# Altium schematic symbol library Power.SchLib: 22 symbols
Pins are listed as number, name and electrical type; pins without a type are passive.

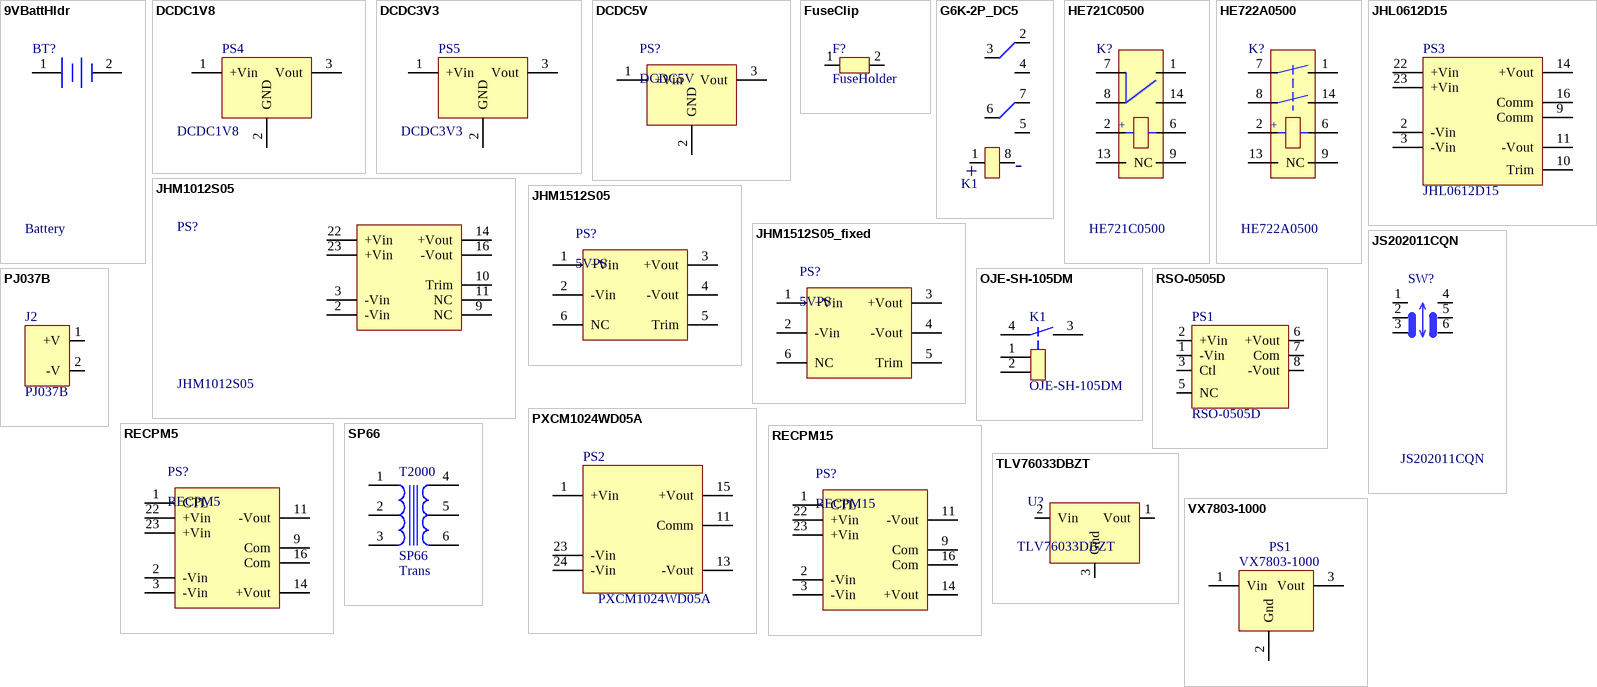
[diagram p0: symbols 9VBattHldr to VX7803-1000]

## 9VBattHldr
designator BT?, comment Battery
Battery Holder (Open) 9V 1 Cell PC Pin; MFG PN: BH9VPC; DK PN: BH9V-PC-ND; MFG: MPD
footprint 9VBattHolder
pins: 1 +, 2 -

## DCDC1V8
designator PS4
Linear Regulator Replacement DC DC Converter 1 Output 1.8V 500mA 4.75V - 28V Input; MFG PN: P7805-Q12-S1R8-S; DK PN: 102-2985-5-ND; MFG: CUI
footprint CUI_P7805
pins: 1 +Vin (power), 2 GND (power), 3 Vout (power)

## DCDC3V3
designator PS5
Linear Regulator Replacement DC DC Converter 1 Output 3.3V 500mA 4.75V - 28V Input; MFG PN: P7805-Q24-S3-S; DK PN: 102-2704-ND; MFG: CUI
footprint CUI_P7805
pins: 1 +Vin (power), 2 GND (power), 3 Vout (power)

## DCDC5V
designator PS?  Comment_1: DCDC5V  (hidden comment: *)
Linear Regulator Replacement DC DC Converter 1 Output 5V 500mA 6.5V - 32V Input; MFG PN: P7805-Q24-S5-S; DK PN: 102-2705-ND; MFG: CUI
footprint CUI_P7805
pins: 1 +Vin (power), 2 GND (power), 3 Vout (power)

## FuseClip
designator F?, comment FuseHolder
Fuse Holder 5A 250V 1 Circuit Cartridge PCB; MFG PN: 4527; MFG: Keystone Electronics; DK PN: 36-4527-ND
footprint FuseClip
pins: 1, 2

## G6K-2P_DC5
designator K1  (value not drawn)
Telecom Relay DPDT (2 Form C) Through Hole; MFG PN: G6K-2P DC5; DK PN: Z116-ND; MFG: Omron
footprint G6K-2P
pins: 1, 2, 3, 4, 5, 6, 7, 8

## HE721C0500
designator K?
RELAY REED SPDT 250MA 5V; DK PN: HE112-ND; MFG: Littlefuse
footprint HE7X
pins: 1, 2, 6, 7, 8, 9, 13 NC, 14

## HE722A0500
designator K?
RELAY REED DPST 500MA 5V; DK PN: HE554-ND; MFG: Littlefuse
footprint HE7X
pins: 1, 2, 6, 7, 8, 9, 13 NC, 14

## JHL0612D15
designator PS3
Isolated Module DC DC Converter 2 Output 15V -15V 200mA, 200mA 10V - 17V Input; MFG: XP Power; DK PN: 1470-3037-5-ND
footprint JHL06
pins: 2 -Vin, 3 -Vin, 9 Comm, 10 Trim, 11 -Vout, 14 +Vout, 16 Comm, 22 +Vin, 23 +Vin

## JHM1012S05
designator PS?
Isolated Module DC DC Converter 1 Output 5V 2A 9V - 18V Input; MFG: XP Power; DK PN: 1470-2051-5-ND
footprint JHM10
pins: 2 -Vin, 3 -Vin, 9 NC, 10 Trim, 11 NC, 14 +Vout, 16 -Vout, 22 +Vin, 23 +Vin

## JHM1512S05
designator PS?, comment 5VPS
Isolated Module DC DC Converter 1 Output 5V 3A 9V - 18V Input; MFG PN: JHM1512S05; DK PN: 1470-2815-5-ND; PKG: JHM15; MFG: XP Power
footprint JMH15
pins: 1 +Vin (power), 2 -Vin (power), 3 +Vout (power), 4 -Vout (power), 5 Trim (power), 6 NC (power)

## JHM1512S05_fixed
designator PS?  Comment_1: 5VPS  (hidden comment: *)
Isolated Module DC DC Converter 1 Output 5V 3A 9V - 18V Input; MFG PN: JHM1512S05; DK PN: 1470-2815-5-ND; PKG: JHM15; MFG: XP Power
footprint JMH15_FIXED
pins: 1 +Vin (power), 2 -Vin (power), 3 +Vout (power), 4 -Vout (power), 5 Trim (power), 6 NC (power)

## JS202011CQN
designator SW?
Slide Switch DPDT Through Hole; DK PN: 401-2001-ND; MFG: C&K
footprint DPDTSlide
pins: 1 15, 2 16, 3 17, 4 18, 5 19, 6 20

## OJE-SH-105DM
designator K1
General Purpose Relay SPST-NO (1 Form A) 5VDC Coil Through Hole; MFG PN: OJE-SH-105DM,000; DK PN: PB874-ND; MFG: TE
footprint OJERELAY
pins: 1, 2, 3, 4
1 alternate drawing of the same symbol

## PJ037B
designator J2
Power Barrel Connector Jack 2.50mm ID (0.098"), 5.50mm OD (0.217") Through Hole, Right Angle; MFG PN: PJ-037B; DK PN: CP-037B-ND; MFG: CUI
footprint PJ037B
pins: 1 +V, 2 -V
1 alternate drawing of the same symbol

## PXCM1024WD05A
designator PS2
Isolated Module DC DC Converter 2 Output 5V -5V 1A, 1A 9V - 36V Input; MFG: TDK Lambda; DK PN: 285-2397-ND
footprint PXCM10
pins: 1 +Vin, 11 Comm, 13 -Vout, 15 +Vout, 23 -Vin, 24 -Vin

## RECPM5
designator PS?  Comment_1: RECPM5  (hidden comment: *)
Isolated Module DC DC Converter 2 Output 5V -5V 500mA, 500mA 9V - 18V Input; MFG PN: REC5-1205DRW/H4/A/SMD; DK PN: REC5-1205DRW/H4/A/SMD-ND; MFG: Recom
footprint REC5-S
pins: 1 CTL (power), 2 -Vin (power), 3 -Vin (power), 9 Com (power), 11 -Vout (power), 14 +Vout (power), 16 Com (power), 22 +Vin (power), 23 +Vin (power)

## RECPM15
designator PS?  Comment_1: RECPM15  (hidden comment: *)
Isolated Module DC DC Converter 2 Output 15V -15V 170mA, 170mA 9V - 18V Input; MFG PN: REC5-1215DRW/H4/A/SMD; DK PN: REC5-1215DRW/H4/A/SMD-ND; MFG: Recom
footprint REC5-S
pins: 1 CTL (power), 2 -Vin (power), 3 -Vin (power), 9 Com (power), 11 -Vout (power), 14 +Vout (power), 16 Com (power), 22 +Vin (power), 23 +Vin (power)

## RSO-0505D
designator PS1
Isolated Module DC DC Converter 2 Output 5V -5V 100mA, 100mA 4.5V - 9V Input; DK PN: 945-1326-ND; MFG: Recom
footprint RECOM-RSO
pins: 1 -Vin, 2 +Vin, 3 Ctl, 5 NC, 6 +Vout, 7 Com, 8 -Vout
1 alternate drawing of the same symbol

## SP66
designator T2000  Comment_1: Trans
XFMR 10K CT/ 10K CT AUDIO; MFG PN: SP-66; DK PN: 237-1151-ND; MFG: Triad Magnetics
footprint SP66
pins: 1, 2, 3, 4, 5, 6

## TLV76033DBZT
designator U?
Linear Voltage Regulator IC 1 Output 100mA SOT-23-3; DK PN: SOT23; MFG: TI
footprint MYSOT23
pins: 1 Vout, 2 Vin, 3 Gnd

## VX7803-1000
designator PS1
Linear Regulator Replacement DC DC Converter 1 Output 3.3V 1A 6V - 36V Input; DK PN: 102-4252-ND; MFG: CUI
footprint VXREG
pins: 1 Vin, 2 Gnd, 3 Vout
1 alternate drawing of the same symbol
